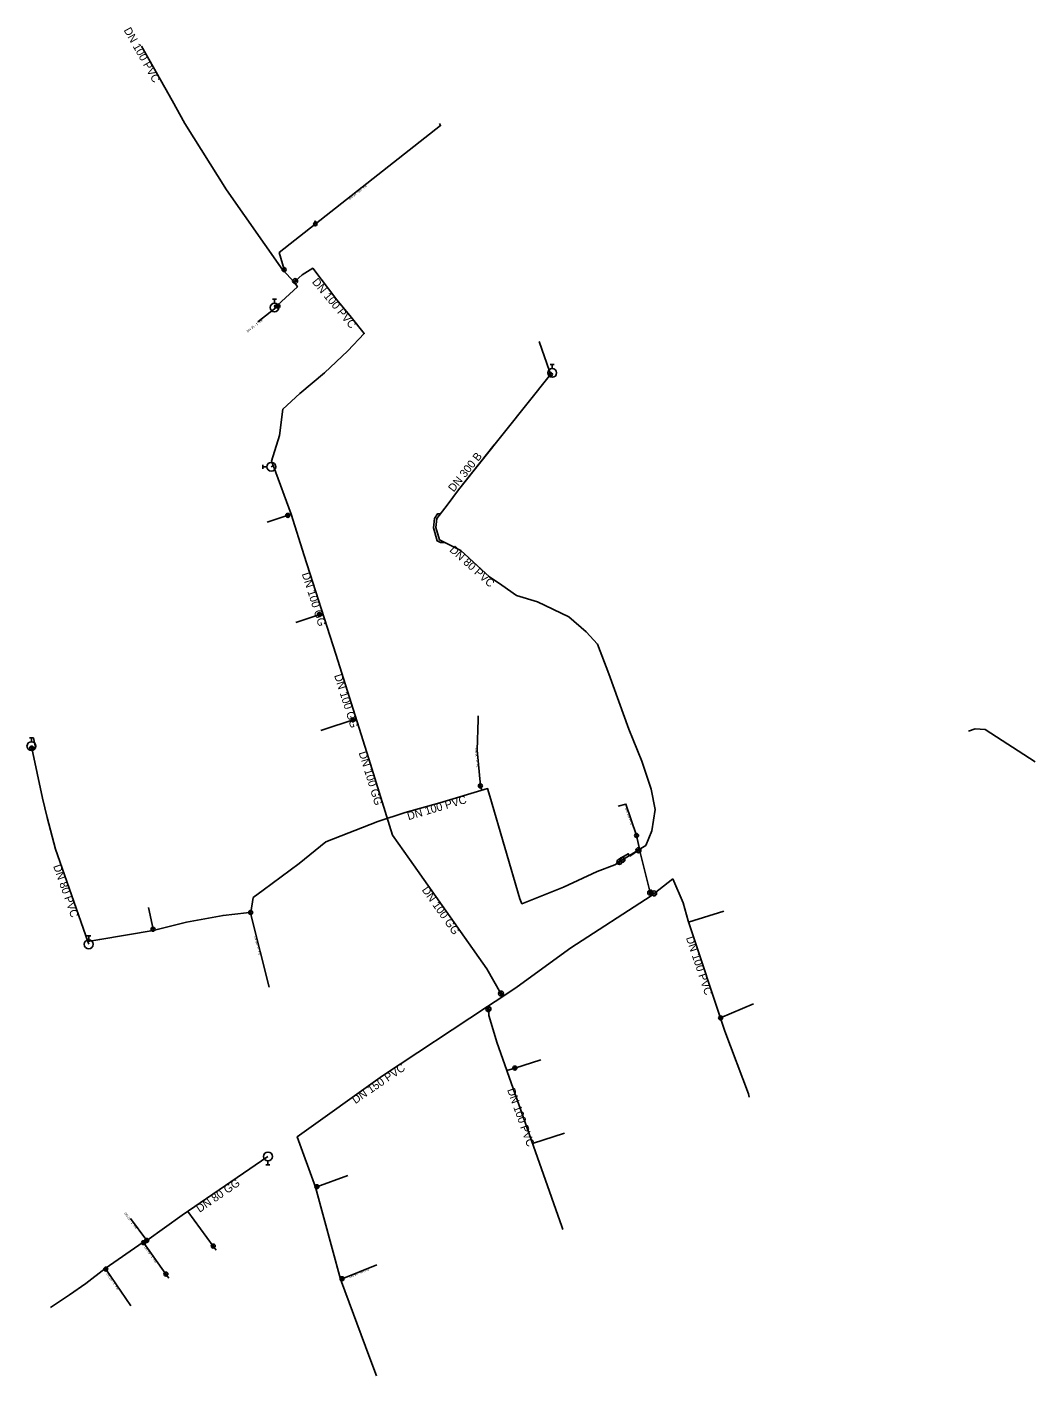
# Model space of a CAD drawing. Extents: x -492371 to -492169, y -1127087 to -1126817.
import ezdxf

# ---------------------------------------------------------------- set-up
doc = ezdxf.new("R2010")
doc.units = 0
for name, color, linetype in [('_hydrantova_odbocka_', 7, 'Continuous'), ('_odpadni_voda_', 7, 'Continuous'), ('_pripojka_prevzato_z_dokumentace_', 7, 'Continuous'), ('_pripojka_priblizne_', 7, 'Continuous'), ('_voda_projekt_smvak_', 7, 'Continuous'), ('_voda_smvak_prevzato_z_dokumentace_', 7, 'Continuous'), ('_vodovodni_chranicka_', 7, 'Continuous'), ('Default', 7, 'Continuous'), ('MoLevel 27', 7, 'Continuous'), ('MoLevel 28', 7, 'Continuous'), ('MoLevel 30', 7, 'Continuous'), ('MoLevel 32', 7, 'Continuous'), ('MoLevel 46', 7, 'Continuous'), ('MoLevel 53', 7, 'Continuous'), ('MoLevel 55', 7, 'Continuous'), ('MoLevel 60', 7, 'Continuous')]:
    doc.layers.add(name, color=color, linetype=linetype)

# ---------------------------------------------------------------- blocks, each defined once
blk = doc.blocks.new('_uzaver_')
at = {"layer": 'Default'}
for p, q in [((-0.000035, -0.000035), (0.000035, 0.000035)), ((0.000035, -0.000035), (-0.000035, 0.000035))]:
    blk.add_line(p, q, dxfattribs=at)
for radius in [0.00005, 0.0000025]:
    blk.add_circle((0, 0), radius, dxfattribs=at)
blk = doc.blocks.new('_uzaver_pripojka_')
at = {"layer": 'Default'}
for p, q in [((-0.000035, -0.000035), (0.000035, 0.000035)), ((0.000035, -0.000035), (-0.000035, 0.000035))]:
    blk.add_line(p, q, dxfattribs=at)
for radius in [0.00005, 0.0000025]:
    blk.add_circle((0, 0), radius, dxfattribs=at)
blk = doc.blocks.new('_hydrant_voda_')
at = {"layer": 'Default'}
for p, q in [((-0.000023, 0.000095), (0.000023, 0.000095)), ((0, 0.000095), (0, 0.00005))]:
    blk.add_line(p, q, dxfattribs=at)
blk.add_circle((0, 0), 0.00005, dxfattribs=at)
blk = doc.blocks.new('_sachta_voda_')
at = {"layer": 'Default'}
blk.add_lwpolyline([(-0.00001, 0.000065), (0, 0.000035), (0.00001, 0.000065)], dxfattribs=at)
blk.add_circle((0, 0), 0.000035, dxfattribs=at)

msp = doc.modelspace()

# ---------------------------------------------------------------- linework, layer by layer
at = {"layer": '_hydrantova_odbocka_'}
msp.add_line((-492358.5, -1126999.97), (-492358.33, -1127000.52), dxfattribs=at)
for points in [[(-492320.46, -1126872.36), (-492320.71, -1126872.52), (-492320.84, -1126872.58), (-492321.08, -1126872.81)], [(-492321.31, -1126904.62), (-492321.46, -1126904.62), (-492321.73, -1126904.75)]]:
    msp.add_lwpolyline(points, dxfattribs=at)
at = {"layer": '_odpadni_voda_'}
msp.add_lwpolyline([(-492168.65, -1126963.93), (-492178.64, -1126957.41), (-492180.67, -1126957.3), (-492181.99, -1126957.75)], dxfattribs=at)
at = {"layer": '_pripojka_prevzato_z_dokumentace_'}
for p, q in [((-492317.76, -1126914.27), (-492322.53, -1126915.87)), ((-492311.43, -1126934.15), (-492316.84, -1126935.96)), ((-492304.72, -1126955.3), (-492311.78, -1126957.67)), ((-492231.04, -1126993.9), (-492238.08, -1126996.07)), ((-492231.67, -1127015.28), (-492225.06, -1127012.47)), ((-492262.96, -1127038.38), (-492269.37, -1127040.44)), ((-492346.71, -1127059.91), (-492349.93, -1127055.51)), ((-492342.86, -1127066.66), (-492342.29, -1127067.48))]:
    msp.add_line(p, q, dxfattribs=at)
for points in [[(-492279.55, -1126969.63), (-492279.82, -1126968.74), (-492280.45, -1126961.56), (-492280.29, -1126955.44), (-492280.24, -1126954.7)], [(-492252.19, -1126972.84), (-492250.65, -1126972.39), (-492248.52, -1126978.69), (-492248, -1126981.1), (-492247.91, -1126981.56)], [(-492267.72, -1127023.67), (-492272.91, -1127025.34), (-492274.52, -1127025.86)], [(-492306.42, -1127046.87), (-492312.6, -1127049.14), (-492312.88, -1127049.25)], [(-492338.49, -1127054.1), (-492333.38, -1127061.03), (-492332.8, -1127061.84)], [(-492347.41, -1127060.25), (-492347.32, -1127060.36), (-492342.86, -1127066.66)], [(-492355, -1127065.53), (-492354.91, -1127065.67), (-492349.88, -1127073.06)]]:
    msp.add_lwpolyline(points, dxfattribs=at)
at = {"layer": '_pripojka_priblizne_'}
for points in [[(-492312.92, -1126856.09), (-492287.81, -1126836.34), (-492287.99, -1126835.91)], [(-492319.4, -1126865.31), (-492319.17, -1126865.21), (-492320.15, -1126861.77), (-492312.92, -1126856.09)], [(-492320.46, -1126872.36), (-492320.4, -1126872.54), (-492324.43, -1126875.68)], [(-492265.79, -1126886.23), (-492265.99, -1126885.61), (-492268.06, -1126879.6)], [(-492369.75, -1126961.18), (-492368.97, -1126961.03), (-492369.39, -1126959.1)], [(-492345.41, -1126997.73), (-492345.43, -1126997.49), (-492346.33, -1126993.11)], [(-492325.86, -1126994.14), (-492325.81, -1126994.56), (-492322.13, -1127009.12)], [(-492307.84, -1127067.71), (-492307.56, -1127067.59), (-492300.56, -1127064.78)]]:
    msp.add_lwpolyline(points, dxfattribs=at)
at = {"layer": '_voda_projekt_smvak_'}
msp.add_lwpolyline([(-492287.84, -1126914.18), (-492288.44, -1126914.22), (-492289.05, -1126915.1), (-492289.21, -1126917), (-492288.48, -1126919.62), (-492287.79, -1126919.95), (-492287.05, -1126919.91)], dxfattribs=at)
at = {"layer": '_voda_smvak_prevzato_z_dokumentace_'}
for p, q in [((-492316.96, -1126867.52), (-492317.13, -1126867.68)), ((-492315.13, -1126922.56), (-492308.82, -1126942.32)), ((-492308.82, -1126942.32), (-492302.18, -1126963.33)), ((-492302.18, -1126963.33), (-492297.46, -1126978.62)), ((-492297.46, -1126978.62), (-492294, -1126983.46)), ((-492247.91, -1126981.56), (-492248.13, -1126981.66)), ((-492245.77, -1126990.15), (-492247.91, -1126981.56)), ((-492294, -1126983.46), (-492278.53, -1127005.42)), ((-492251.68, -1126983.8), (-492251.97, -1126984)), ((-492241.24, -1126987.36), (-492245, -1126990.33)), ((-492245.57, -1126990.78), (-492245.77, -1126990.15)), ((-492245, -1126990.33), (-492245.57, -1126990.78)), ((-492278.53, -1127005.42), (-492275.69, -1127010.39)), ((-492275.34, -1127011), (-492278.41, -1127013.02)), ((-492275.69, -1127010.39), (-492275.34, -1127011)), ((-492278.41, -1127013.02), (-492278.21, -1127013.51))]:
    msp.add_line(p, q, dxfattribs=at)
for points in [[(-492347.72, -1126820.38), (-492341.6, -1126831.28), (-492339.04, -1126835.9), (-492330.72, -1126849.19), (-492319.4, -1126865.31), (-492317.13, -1126867.68)], [(-492319.43, -1126893.17), (-492316.03, -1126890.04), (-492311.09, -1126885.93), (-492306.42, -1126881.48), (-492303.11, -1126878.05), (-492305.73, -1126874.76), (-492308.61, -1126871.29), (-492313.42, -1126864.93), (-492315.54, -1126866.25), (-492316.96, -1126867.52)], [(-492317.13, -1126867.68), (-492316.49, -1126868.69), (-492320.46, -1126872.36)], [(-492265.42, -1126885.93), (-492265.79, -1126886.23), (-492284.2, -1126909.37)], [(-492321.31, -1126904.62), (-492321.68, -1126903.64), (-492320.09, -1126898.49), (-492319.43, -1126893.17)], [(-492321.31, -1126904.62), (-492317.76, -1126914.27), (-492315.13, -1126922.56)], [(-492284.2, -1126909.37), (-492286.49, -1126912.43), (-492288.56, -1126915.11), (-492288.74, -1126916.96), (-492288.04, -1126919.42), (-492283.77, -1126921.56), (-492278, -1126926.8), (-492275.52, -1126928.5), (-492272.56, -1126930.6), (-492268.38, -1126931.84), (-492262.09, -1126934.84), (-492258.65, -1126937.86)], [(-492258.65, -1126937.86), (-492256.33, -1126940.3), (-492254.09, -1126946.25), (-492250.05, -1126957.35), (-492247.46, -1126963.78), (-492245.58, -1126969.4), (-492244.82, -1126973.51), (-492245.46, -1126977.74), (-492246.68, -1126980.72), (-492247.68, -1126981.31), (-492251.34, -1126983.56)], [(-492358.5, -1126999.97), (-492364.96, -1126981.41), (-492366.67, -1126975.11), (-492367.57, -1126971.21), (-492369.75, -1126961.18), (-492369.82, -1126960.77)], [(-492251.97, -1126984), (-492252.87, -1126984.56), (-492256.42, -1126985.91), (-492263.13, -1126989.09), (-492271.49, -1126992.4), (-492271.92, -1126991.4), (-492277.91, -1126970.81), (-492278.39, -1126969.28), (-492287.98, -1126972.12), (-492294.89, -1126974.08), (-492300.39, -1126975.87), (-492310.81, -1126979.94), (-492316.12, -1126984.31), (-492323.33, -1126989.68), (-492325.37, -1126991.12)], [(-492248.13, -1126981.66), (-492249.86, -1126982.82), (-492250.17, -1126982.36), (-492251.94, -1126983.36), (-492251.68, -1126983.8)], [(-492251.34, -1126983.56), (-492251.39, -1126983.59), (-492251.68, -1126983.8)], [(-492225.92, -1127031.19), (-492226.1, -1127030.53), (-492230.81, -1127017.94), (-492238.16, -1126995.84), (-492239.16, -1126992.2), (-492241.24, -1126987.36)], [(-492325.37, -1126991.12), (-492325.86, -1126994.14), (-492326.71, -1126994.24), (-492331.41, -1126994.74), (-492338.74, -1126996.09), (-492345.41, -1126997.73), (-492356.12, -1126999.53), (-492358.5, -1126999.97)], [(-492245.57, -1126990.78), (-492261.68, -1127001.2), (-492272.42, -1127009.07), (-492275.34, -1127011)], [(-492278.41, -1127013.02), (-492299.41, -1127026.89), (-492316.58, -1127039.15), (-492312.88, -1127049.25), (-492307.84, -1127067.71), (-492302.01, -1127083.53), (-492300.62, -1127087.1)], [(-492278.21, -1127013.51), (-492278.11, -1127014.81), (-492277.09, -1127018.33), (-492276.55, -1127020.13), (-492263.48, -1127057.09), (-492263.27, -1127057.7)], [(-492322.4, -1127043.06), (-492339.63, -1127054.87), (-492346.71, -1127059.91), (-492347.41, -1127060.25), (-492355, -1127065.53), (-492358.9, -1127068.53), (-492362.16, -1127070.83), (-492366.02, -1127073.37)]]:
    msp.add_lwpolyline(points, dxfattribs=at)
at = {"layer": '_vodovodni_chranicka_'}
msp.add_lwpolyline([(-492286.49, -1126912.43), (-492284.2, -1126909.37), (-492277.04, -1126900.37)], dxfattribs=at)

# ---------------------------------------------------------------- block references
at = {"layer": 'MoLevel 27'}
for p, xscale, yscale, rotation in [((-492316.96, -1126867.52), 10000, 10000, 36.4841374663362), ((-492248.13, -1126981.66), 10000.000000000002, 10000, -159.03396730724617), ((-492251.97, -1126984), 10000, 10000, 35.49542981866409), ((-492245.77, -1126990.15), 10000, 10000, -72.123597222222), ((-492275.69, -1127010.39), 10000, 10000.000000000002, 119.76018626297), ((-492278.21, -1127013.51), 10000, 10000, -71.69667222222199)]:
    msp.add_blockref('_uzaver_', p, dxfattribs=dict(at, xscale=xscale, yscale=yscale, rotation=rotation))
for p, xscale, yscale in [((-492320.84, -1126872.58), 5000, 5000), ((-492251.34, -1126983.56), 10000, 10000), ((-492245, -1126990.33), 10000, 10000)]:
    msp.add_blockref('_uzaver_', p, dxfattribs=dict(at, xscale=xscale, yscale=yscale))
at = {"layer": 'MoLevel 28', "xscale": 17636.68430335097, "yscale": 17636.68430335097}
for p in [(-492321.08, -1126872.81), (-492265.42, -1126885.93), (-492369.82, -1126960.77), (-492358.33, -1127000.52)]:
    msp.add_blockref('_hydrant_voda_', p, dxfattribs=at)
for p, rotation in [((-492321.73, -1126904.75), 90), ((-492322.4, -1127043.06), 180)]:
    msp.add_blockref('_hydrant_voda_', p, dxfattribs=dict(at, rotation=rotation))
at = {"layer": 'MoLevel 30', "xscale": 10000, "yscale": 10000}
msp.add_blockref('_sachta_voda_', (-492312.92, -1126856.09), dxfattribs=at)
at = {"layer": 'MoLevel 53', "xscale": 7999.999999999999, "yscale": 7999.999999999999}
for p in [(-492319.17, -1126865.21), (-492320.4, -1126872.54), (-492265.79, -1126886.23), (-492369.75, -1126961.18), (-492279.82, -1126968.74), (-492248.52, -1126978.69), (-492325.86, -1126994.14), (-492345.43, -1126997.49), (-492347.32, -1127060.36)]:
    msp.add_blockref('_uzaver_pripojka_', p, dxfattribs=at)
at = {"layer": 'MoLevel 53'}
for p, xscale, yscale, rotation in [((-492318.42, -1126914.5), 7999.999999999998, 7999.999999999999, -161.550708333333), ((-492312.09, -1126934.38), 7999.999999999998, 7999.999999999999, -161.550708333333), ((-492305.38, -1126955.52), 7999.999999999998, 7999.999999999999, -161.550708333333), ((-492231.67, -1127015.28), 7999.999999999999, 7999.999999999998, -161.88482500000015), ((-492272.91, -1127025.34), 7999.999999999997, 8000, 18.204616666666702), ((-492312.6, -1127049.14), 7999.999999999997, 8000, 18.204616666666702), ((-492346.71, -1127059.91), 8000.000000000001, 7999.999999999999, -55.519736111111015), ((-492333.38, -1127061.03), 7999.999999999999, 8000.000000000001, 34.1977), ((-492354.91, -1127065.67), 7999.999999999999, 8000, -56.444458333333), ((-492342.86, -1127066.66), 7999.999999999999, 8000.000000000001, 34.1977), ((-492307.56, -1127067.59), 7999.999999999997, 8000, 18.204616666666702)]:
    msp.add_blockref('_uzaver_pripojka_', p, dxfattribs=dict(at, xscale=xscale, yscale=yscale, rotation=rotation))

# ---------------------------------------------------------------- texts
at = {"layer": 'MoLevel 32'}
for s, rotation, p in [("DN 32 - 5/4'' PE", 38.1778, (-492306.02, -1126851.24)), ("DN 25 - 1'' PE", 37.9128, (-492326.46, -1126877.84)), ("DN 50 - 2'' PE", 284.184, (-492325.19, -1126998.86)), ('DN 40 - 6/4 PE', 21.8733, (-492306.01, -1127067.46))]:
    msp.add_text(s, height=0.455, rotation=rotation, dxfattribs=at).set_placement(p)
at = {"layer": 'MoLevel 46'}
for s, rotation, p in [('DN 100 PVC', 299.3222, (-492351.36, -1126817.18)), ('DN 100 PVC', 309.7275, (-492313.66, -1126867.73)), ('DN 80 PVC', 317.8282, (-492286.12, -1126921.6)), ('DN 100 GG', 287.7238, (-492315.64, -1126926.23)), ('DN 100 GG', 287.5404, (-492309.15, -1126946.6)), ('DN 100 GG', 287.1306, (-492304.23, -1126962.1)), ('DN 100 PVC', 16.4861, (-492294.23, -1126975.64)), ('DN 80 PVC', 289.204, (-492365.47, -1126984.83)), ('DN 100 GG', 305.1636, (-492291.63, -1126989.62)), ('DN 100 PVC', 288.4044, (-492238.63, -1126999.22)), ('DN 150 PVC', 34.4783, (-492304.87, -1127032.59)), ('DN 100 PVC', 289.4749, (-492274.48, -1127029.7)), ('DN 80 GG', 34.4364, (-492336.1, -1127054.39))]:
    msp.add_text(s, height=1.605, rotation=rotation, dxfattribs=at).set_placement(p)
at = {"layer": 'MoLevel 55'}
for s, rotation, p in [("DN 50 - 2'' PE", 275.0145, (-492280.93, -1126961.26)), ('DN 100 PVC', 288.672, (-492250.83, -1126973.27)), ("DN 25 - 1'' PE", 306.1973, (-492351.24, -1127054.49)), ("DN 25 - 1'' Pb", 305.2797, (-492347.23, -1127061.27)), ("DN 25 - 1'' PE", 304.2504, (-492354.82, -1127066.62))]:
    msp.add_text(s, height=0.455, rotation=rotation, dxfattribs=at).set_placement(p)
at = {"layer": 'MoLevel 60'}
msp.add_text('DN 300 B', height=1.605, rotation=51.5051, dxfattribs=at).set_placement((-492285.18, -1126909.93))

doc.saveas('drawing.dxf')
